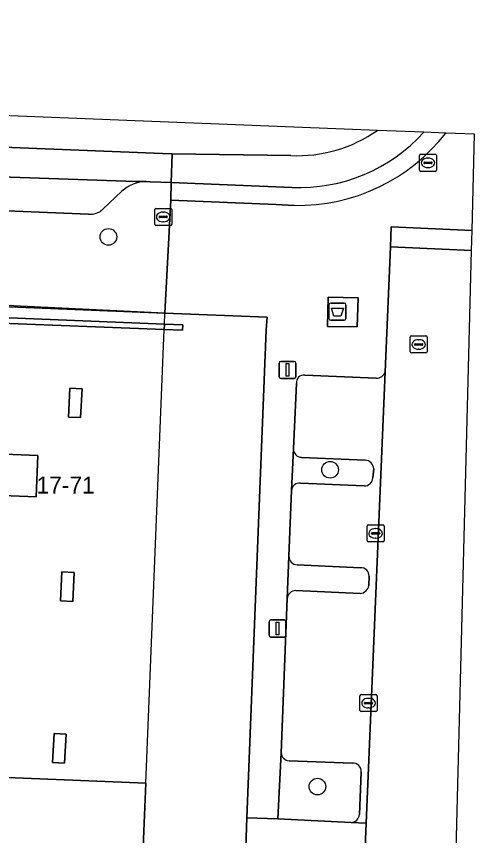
# Model space of a CAD drawing. Extents: x 160888 to 161385, y 386490 to 386908.
# Drawn here: x 161269.97 to 161296.87, y 386854.34 to 386902.41 of the extents above; entities that cross this region are included whole.
import ezdxf

# ---------------------------------------------------------------- set-up
doc = ezdxf.new("R2010")
doc.units = 0
for name, color, linetype in [('IMGEO_Afval_apart_plaats', 7, 'Continuous'), ('IMGEO_Boom', 7, 'Continuous'), ('IMGEO_Erf', 7, 'Continuous'), ('IMGEO_Groenvoorziening', 7, 'Continuous'), ('IMGEO_Hek', 7, 'Continuous'), ('IMGEO_Kolk', 7, 'Continuous'), ('IMGEO_Lichtmast', 7, 'Continuous'), ('IMGEO_Muur', 7, 'Continuous'), ('IMGEO_Pand', 7, 'Continuous'), ('IMGEO_Pand_nummerreeks', 7, 'Continuous'), ('IMGEO_Pand_overbouw', 7, 'Continuous'), ('IMGEO_Parkeervlak_gesloten', 7, 'Continuous'), ('IMGEO_Parkeervlak_open', 7, 'Continuous'), ('IMGEO_Rijbaan_lokaal_gesloten', 7, 'Continuous'), ('IMGEO_Rijbaan_lokaal_open', 7, 'Continuous'), ('IMGEO_Rioolput', 7, 'Continuous'), ('IMGEO_Voetpad_gesloten', 7, 'Continuous'), ('IMGEO_Voetpad_open', 7, 'Continuous')]:
    doc.layers.add(name, color=color, linetype=linetype)

msp = doc.modelspace()

# ---------------------------------------------------------------- linework, layer by layer
at = {"layer": 'IMGEO_Afval_apart_plaats'}
for p, q in [((161288.323, 386884.683), (161288.323, 386885.483)), ((161288.323, 386885.483), (161288.323, 386884.683)), ((161288.423, 386885.583), (161289.213, 386885.583)), ((161289.213, 386885.583), (161288.423, 386885.583)), ((161289.313, 386885.483), (161289.313, 386884.683)), ((161289.313, 386884.683), (161289.313, 386885.483)), ((161289.213, 386884.583), (161288.423, 386884.583)), ((161288.423, 386884.583), (161289.213, 386884.583))]:
    msp.add_line(p, q, dxfattribs=at)
msp.add_lwpolyline([(161288.466, 386885.297), (161289.17, 386885.297), (161289.021, 386884.827), (161288.615, 386884.827), (161288.466, 386885.297)], dxfattribs=at)
for centre, start, end in [((161288.423, 386885.483), 90, 180), ((161288.423, 386885.483), 90, 180), ((161289.213, 386885.483), 0, 90), ((161289.213, 386885.483), 360, 90), ((161288.423, 386884.683), 180, 270), ((161288.423, 386884.683), 180, 270), ((161289.213, 386884.683), 270, 0), ((161289.213, 386884.683), 270, 0)]:
    msp.add_arc(centre, 0.1, start, end, dxfattribs=at)
at = {"layer": 'IMGEO_Boom'}
for centre in [(161275.373, 386889.471), (161288.387, 386875.804), (161287.645, 386857.215)]:
    msp.add_circle(centre, 0.489, dxfattribs=at)
at = {"layer": 'IMGEO_Erf'}
for points in [[(161256.153, 386885.234), (161268.567, 386884.752), (161278.663, 386884.36), (161279.736, 386884.318), (161279.724, 386883.998), (161278.65, 386884.04), (161268.554, 386884.432), (161256.14, 386884.914)], [(161273.109, 386880.597), (161273.827, 386880.563), (161273.745, 386878.865), (161273.027, 386878.899)], [(161268.243, 386876.619), (161268.307, 386876.617), (161268.249, 386876.768), (161271.239, 386876.642), (161271.137, 386874.214), (161268.151, 386874.333), (161268.226, 386874.47), (161268.157, 386874.473)], [(161272.649, 386869.817), (161273.366, 386869.782), (161273.284, 386868.084), (161272.566, 386868.119)], [(161272.189, 386860.326), (161272.892, 386860.289), (161272.802, 386858.591), (161272.099, 386858.628)]]:
    msp.add_lwpolyline(points, close=True, dxfattribs=at)
msp.add_lwpolyline([(161267.493, 386857.839), (161277.574, 386857.417), (161277.385, 386852.718), (161283.395, 386852.488), (161283.497, 386855.383), (161284.645, 386884.014), (161284.686, 386884.758), (161278.689, 386885.003), (161268.594, 386885.414)], dxfattribs=at)
at = {"layer": 'IMGEO_Groenvoorziening'}
for points in [[(161286.232, 386877.048), (161286.131, 386874.595)], [(161290.445, 386876.371), (161286.716, 386876.537)], [(161290.902, 386875.327), (161290.948, 386875.86)], [(161286.642, 386875.03), (161290.395, 386874.859)], [(161285.97, 386870.742), (161285.872, 386868.246)], [(161290.183, 386870.06), (161286.454, 386870.23)], [(161290.661, 386869.015), (161290.68, 386869.559)], [(161286.385, 386868.722), (161290.145, 386868.551)], [(161285.519, 386859.207), (161285.322, 386855.328), (161289.625, 386855.121)], [(161289.691, 386858.597), (161285.989, 386858.735)], [(161290.109, 386855.573), (161290.208, 386858.067)]]:
    msp.add_lwpolyline(points, dxfattribs=at)
for centre, radius, start, end in [((161286.732, 386877.037), 0.5, 178.7551, 268.1361), ((161290.415, 386875.839), 0.533, 2.277, 86.8189), ((161290.409, 386875.353), 0.494, 268.4026, 357.0162), ((161286.602, 386874.559), 0.473, 85.1814, 175.6322), ((161286.479, 386870.739), 0.509, 179.6262, 267.1532), ((161290.193, 386869.573), 0.487, 358.3454, 91.1954), ((161290.115, 386869.103), 0.553, 273.0723, 350.853), ((161286.392, 386868.201), 0.522, 90.7175, 174.9974), ((161286.003, 386859.218), 0.484, 181.3596, 268.3971), ((161289.728, 386858.116), 0.483, 354.2201, 94.3572), ((161289.622, 386855.609), 0.488, 270.3229, 355.761)]:
    msp.add_arc(centre, radius, start, end, dxfattribs=at)
at = {"layer": 'IMGEO_Hek'}
msp.add_lwpolyline([(161284.645, 386884.014), (161283.497, 386855.383)], dxfattribs=at)
at = {"layer": 'IMGEO_Kolk'}
for p, q in [((161278.09, 386890.218), (161278.09, 386891.07)), ((161278.165, 386891.144), (161279.017, 386891.144)), ((161278.578, 386890.924), (161278.603, 386890.924)), ((161279.091, 386891.07), (161279.091, 386890.218)), ((161278.349, 386890.638), (161278.349, 386890.65)), ((161278.787, 386890.601), (161278.389, 386890.601)), ((161278.392, 386890.687), (161278.79, 386890.687)), ((161278.833, 386890.65), (161278.833, 386890.638)), ((161279.017, 386890.144), (161278.165, 386890.144)), ((161278.601, 386890.364), (161278.576, 386890.364)), ((161290.56, 386871.649), (161290.56, 386872.501)), ((161290.635, 386872.575), (161291.487, 386872.575)), ((161291.048, 386872.355), (161291.073, 386872.355)), ((161291.561, 386872.501), (161291.561, 386871.649)), ((161290.819, 386872.069), (161290.819, 386872.081)), ((161291.257, 386872.032), (161290.859, 386872.032)), ((161290.862, 386872.118), (161291.26, 386872.118)), ((161291.071, 386871.795), (161291.046, 386871.795)), ((161291.303, 386872.081), (161291.303, 386872.069)), ((161291.487, 386871.575), (161290.635, 386871.575)), ((161290.218, 386862.617), (161291.07, 386862.617)), ((161290.143, 386861.691), (161290.143, 386862.543)), ((161290.402, 386862.111), (161290.402, 386862.123)), ((161290.84, 386862.074), (161290.442, 386862.074)), ((161290.445, 386862.16), (161290.843, 386862.16)), ((161290.631, 386862.397), (161290.656, 386862.397)), ((161290.886, 386862.123), (161290.886, 386862.111)), ((161291.144, 386862.543), (161291.144, 386861.691)), ((161291.07, 386861.617), (161290.218, 386861.617)), ((161290.654, 386861.837), (161290.629, 386861.837))]:
    msp.add_line(p, q, dxfattribs=at)
for points in [[(161278.09, 386890.218), (161278.09, 386891.07)], [(161278.165, 386891.144), (161279.017, 386891.144)], [(161279.091, 386891.07), (161279.091, 386890.218)], [(161279.017, 386890.144), (161278.165, 386890.144)], [(161290.56, 386871.649), (161290.56, 386872.501)], [(161290.635, 386872.575), (161291.487, 386872.575)], [(161291.561, 386872.501), (161291.561, 386871.649)], [(161291.487, 386871.575), (161290.635, 386871.575)], [(161290.218, 386862.617), (161291.07, 386862.617)], [(161290.143, 386861.691), (161290.143, 386862.543)], [(161291.144, 386862.543), (161291.144, 386861.691)], [(161291.07, 386861.617), (161290.218, 386861.617)]]:
    msp.add_lwpolyline(points, dxfattribs=at)
for centre, radius, start, end in [((161278.167, 386891.068), 0.0765, 91.552, 178.448), ((161278.167, 386891.068), 0.0765, 91.552, 178.448), ((161279.015, 386891.068), 0.0765, 1.552, 88.448), ((161279.015, 386891.068), 0.0765, 1.552, 88.448), ((161278.389, 386890.647), 0.0403, 85.8775, 175.7526), ((161278.386, 386890.637), 0.0366, 178.938, 274.7102), ((161278.79, 386890.644), 0.043, 264.8664, 352.4533), ((161278.794, 386890.649), 0.0386, 1.7309, 96.639), ((161278.167, 386890.22), 0.0765, 181.552, 268.448), ((161278.167, 386890.22), 0.0765, 181.552, 268.448), ((161279.015, 386890.22), 0.0765, 271.552, 358.448), ((161279.015, 386890.22), 0.0765, 271.552, 358.448), ((161290.637, 386872.499), 0.0765, 91.552, 178.448), ((161290.637, 386872.499), 0.0765, 91.552, 178.448), ((161291.485, 386872.499), 0.0765, 1.552, 88.448), ((161291.485, 386872.499), 0.0765, 1.552, 88.448), ((161290.859, 386872.078), 0.0403, 85.8775, 175.7526), ((161290.856, 386872.068), 0.0366, 178.938, 274.7102), ((161291.26, 386872.075), 0.043, 264.8664, 352.4533), ((161291.264, 386872.08), 0.0386, 1.7309, 96.639), ((161290.637, 386871.651), 0.0765, 181.552, 268.448), ((161290.637, 386871.651), 0.0765, 181.552, 268.448), ((161291.485, 386871.651), 0.0765, 271.552, 358.448), ((161291.485, 386871.651), 0.0765, 271.552, 358.448), ((161290.22, 386862.541), 0.0765, 91.552, 178.448), ((161290.22, 386862.541), 0.0765, 91.552, 178.448), ((161291.068, 386862.541), 0.0765, 1.552, 88.448), ((161291.068, 386862.541), 0.0765, 1.552, 88.448), ((161290.442, 386862.12), 0.0403, 85.8775, 175.7526), ((161290.439, 386862.11), 0.0366, 178.938, 274.7102), ((161290.843, 386862.117), 0.043, 264.8664, 352.4533), ((161290.847, 386862.122), 0.0386, 1.7309, 96.639), ((161290.22, 386861.693), 0.0765, 181.552, 268.448), ((161290.22, 386861.693), 0.0765, 181.552, 268.448), ((161291.068, 386861.693), 0.0765, 271.552, 358.448), ((161291.068, 386861.693), 0.0765, 271.552, 358.448)]:
    msp.add_arc(centre, radius, start, end, dxfattribs=at)
for centre, major_axis, ratio, start_param, end_param in [((161278.577, 386890.644), (-0.387, 0.002), 0.722429, 4.712389, 7.853982), ((161278.602, 386890.644), (-0.39, 0.002), 0.717154, 1.570796, 4.712389), ((161291.047, 386872.075), (-0.387, 0.002), 0.722429, 4.712389, 7.853982), ((161291.072, 386872.075), (-0.39, 0.002), 0.717154, 1.570796, 4.712389), ((161290.63, 386862.117), (-0.387, 0.002), 0.722429, 4.712389, 7.853982), ((161290.655, 386862.117), (-0.39, 0.002), 0.717154, 1.570796, 4.712389)]:
    msp.add_ellipse(centre, major_axis=major_axis, ratio=ratio, start_param=start_param, end_param=end_param, dxfattribs=at)
at = {"layer": 'IMGEO_Lichtmast'}
for p, q in [((161285.393, 386881.265), (161285.393, 386882.065)), ((161285.393, 386882.065), (161285.393, 386881.265)), ((161285.493, 386882.165), (161286.283, 386882.165)), ((161286.283, 386882.165), (161285.493, 386882.165)), ((161286.383, 386882.065), (161286.383, 386881.265)), ((161286.383, 386881.265), (161286.383, 386882.065)), ((161286.283, 386881.165), (161285.493, 386881.165)), ((161285.493, 386881.165), (161286.283, 386881.165)), ((161284.806, 386866.095), (161284.806, 386866.895)), ((161284.806, 386866.895), (161284.806, 386866.095)), ((161284.906, 386866.995), (161285.696, 386866.995)), ((161285.696, 386866.995), (161284.906, 386866.995)), ((161285.796, 386866.895), (161285.796, 386866.095)), ((161285.796, 386866.095), (161285.796, 386866.895)), ((161285.696, 386865.995), (161284.906, 386865.995)), ((161284.906, 386865.995), (161285.696, 386865.995))]:
    msp.add_line(p, q, dxfattribs=at)
for points in [[(161285.813, 386882.04), (161285.963, 386882.04), (161285.963, 386881.29), (161285.813, 386881.29), (161285.813, 386882.04)], [(161285.226, 386866.87), (161285.376, 386866.87), (161285.376, 386866.12), (161285.226, 386866.12), (161285.226, 386866.87)]]:
    msp.add_lwpolyline(points, dxfattribs=at)
for centre, start, end in [((161285.493, 386882.065), 90, 180), ((161285.493, 386882.065), 90, 180), ((161286.283, 386882.065), 0, 90), ((161286.283, 386882.065), 360, 90), ((161285.493, 386881.265), 180, 270), ((161285.493, 386881.265), 180, 270), ((161286.283, 386881.265), 270, 0), ((161286.283, 386881.265), 270, 0), ((161284.906, 386866.895), 90, 180), ((161284.906, 386866.895), 90, 180), ((161285.696, 386866.895), 0, 90), ((161285.696, 386866.895), 360, 90), ((161284.906, 386866.095), 180, 270), ((161284.906, 386866.095), 180, 270), ((161285.696, 386866.095), 270, 0), ((161285.696, 386866.095), 270, 0)]:
    msp.add_arc(centre, 0.1, start, end, dxfattribs=at)
at = {"layer": 'IMGEO_Muur'}
for points in [[(161268.567, 386884.752), (161268.554, 386884.432), (161278.65, 386884.04), (161278.663, 386884.36)], [(161279.724, 386883.998), (161279.736, 386884.318), (161278.663, 386884.36), (161278.65, 386884.04)]]:
    msp.add_lwpolyline(points, close=True, dxfattribs=at)
at = {"layer": 'IMGEO_Pand'}
msp.add_lwpolyline([(161208.047, 386882.906), (161205.549, 386883.004), (161205.23, 386883.017), (161203.943, 386850.322), (161203.707, 386843.159), (161282.19, 386840.045), (161283.986, 386839.974), (161284.468, 386852.014), (161284.901, 386852.005), (161284.908, 386852.43), (161283.395, 386852.488), (161277.385, 386852.718), (161277.574, 386857.417), (161267.493, 386857.839), (161267.366, 386854.695), (161257.979, 386855.044), (161254.641, 386855.168), (161254.804, 386859.3), (161254.82, 386859.706), (161248.886, 386860.967), (161238.86, 386863.105)], dxfattribs=at)
for points in [[(161273.827, 386880.563), (161273.109, 386880.597), (161273.027, 386878.899), (161273.745, 386878.865)], [(161271.137, 386874.214), (161271.239, 386876.642), (161268.249, 386876.768), (161268.307, 386876.617), (161268.243, 386876.619), (161268.157, 386874.473), (161268.226, 386874.47), (161268.151, 386874.333)], [(161272.649, 386869.817), (161272.566, 386868.119), (161273.284, 386868.084), (161273.366, 386869.782)], [(161272.892, 386860.289), (161272.189, 386860.326), (161272.099, 386858.628), (161272.802, 386858.591)]]:
    msp.add_lwpolyline(points, close=True, dxfattribs=at)
at = {"layer": 'IMGEO_Pand_overbouw'}
msp.add_lwpolyline([(161268.597, 386885.494), (161268.594, 386885.414), (161268.567, 386884.752), (161268.554, 386884.432), (161268.249, 386876.768), (161271.239, 386876.642), (161271.137, 386874.214), (161268.151, 386874.333), (161267.493, 386857.839), (161277.574, 386857.417), (161278.65, 386884.04), (161278.663, 386884.36), (161278.689, 386885.003)], close=True, dxfattribs=at)
at = {"layer": 'IMGEO_Parkeervlak_gesloten'}
for points in [[(161277.593, 386892.717), (161276.971, 386892.717), (161258.887, 386893.342), (161258.81, 386891.423), (161274.2, 386890.804)], [(161275.046, 386891.089), (161276.17, 386892.15)]]:
    msp.add_lwpolyline(points, dxfattribs=at)
for centre, radius, start, end in [((161277.62, 386890.58), 2.137, 90.723, 132.727), ((161274.309, 386891.879), 1.08, 264.2072, 313.028)]:
    msp.add_arc(centre, radius, start, end, dxfattribs=at)
at = {"layer": 'IMGEO_Parkeervlak_open'}
for points in [[(161291.087, 386881.182), (161286.903, 386881.36)], [(161289.625, 386855.121), (161290.502, 386855.078), (161291.625, 386881.556)], [(161286.409, 386880.878), (161286.232, 386877.048)], [(161286.716, 386876.537), (161290.445, 386876.371)], [(161290.948, 386875.86), (161290.902, 386875.327)], [(161286.131, 386874.595), (161285.97, 386870.742)], [(161290.395, 386874.859), (161286.642, 386875.03)], [(161286.454, 386870.23), (161290.183, 386870.06)], [(161290.68, 386869.559), (161290.661, 386869.015)], [(161290.145, 386868.551), (161286.385, 386868.722)], [(161285.872, 386868.246), (161285.519, 386859.207)], [(161285.989, 386858.735), (161289.691, 386858.597)], [(161290.208, 386858.067), (161290.109, 386855.573)]]:
    msp.add_lwpolyline(points, dxfattribs=at)
for centre, radius, start, end in [((161286.86, 386880.91), 0.453, 84.5982, 183.9929), ((161291.109, 386881.725), 0.543, 267.73, 341.8815), ((161286.732, 386877.037), 0.5, 178.7551, 268.1361), ((161290.415, 386875.839), 0.533, 2.277, 86.8189), ((161290.409, 386875.353), 0.494, 268.4026, 357.0162), ((161286.602, 386874.559), 0.473, 85.1814, 175.6322), ((161286.479, 386870.739), 0.509, 179.6262, 267.1532), ((161290.193, 386869.573), 0.487, 358.3454, 91.1954), ((161290.115, 386869.103), 0.553, 273.0723, 350.853), ((161286.392, 386868.201), 0.522, 90.7175, 174.9974), ((161286.003, 386859.218), 0.484, 181.3596, 268.3971), ((161289.728, 386858.116), 0.483, 354.2201, 94.3572), ((161289.622, 386855.609), 0.488, 270.3229, 355.761)]:
    msp.add_arc(centre, radius, start, end, dxfattribs=at)
at = {"layer": 'IMGEO_Rijbaan_lokaal_gesloten'}
for points in [[(161291.165, 386895.721), (161123.374, 386902.409), (161123.263, 386900.56), (161248.069, 386895.57), (161278.544, 386894.358), (161279.11, 386894.349), (161286.088, 386894.243)], [(161293.896, 386895.612), (161291.165, 386895.721)], [(161286.088, 386894.243), (161279.11, 386894.349), (161279.059, 386892.659), (161286.148, 386892.369)]]:
    msp.add_lwpolyline(points, dxfattribs=at)
msp.add_lwpolyline([(161279.11, 386894.349), (161278.544, 386894.358), (161248.069, 386895.57), (161123.263, 386900.56), (161123.188, 386898.901), (161155.904, 386897.594), (161176.778, 386896.8), (161194.86, 386896.072), (161209.056, 386895.484), (161221.008, 386894.938), (161241.882, 386894.123), (161247.927, 386893.867), (161258.887, 386893.342), (161276.971, 386892.717), (161277.593, 386892.717), (161277.832, 386892.705), (161279.059, 386892.659)], close=True, dxfattribs=at)
for centre, radius, start, end in [((161286.454, 386902.445), 8.211, 267.4462, 305.0109), ((161286.454, 386902.445), 8.211, 267.4462, 305.0109), ((161286.549, 386902.289), 9.928, 267.6839, 317.7351)]:
    msp.add_arc(centre, radius, start, end, dxfattribs=at)
at = {"layer": 'IMGEO_Rijbaan_lokaal_open'}
for points in [[(161295.749, 386851.961), (161296.697, 386888.665), (161296.697, 386888.665), (161291.93, 386888.882), (161291.625, 386881.556), (161290.502, 386855.078), (161290.382, 386852.207), (161293.804, 386852.031)], [(161283.497, 386855.383), (161283.395, 386852.488), (161284.908, 386852.43), (161290.382, 386852.207), (161290.502, 386855.078), (161289.625, 386855.121), (161285.322, 386855.328)]]:
    msp.add_lwpolyline(points, close=True, dxfattribs=at)
at = {"layer": 'IMGEO_Rioolput'}
for p, q in [((161293.71, 386894.317), (161294.562, 386894.317)), ((161293.635, 386893.391), (161293.635, 386894.243)), ((161293.894, 386893.811), (161293.894, 386893.823)), ((161293.937, 386893.86), (161294.335, 386893.86)), ((161294.123, 386894.097), (161294.148, 386894.097)), ((161294.378, 386893.823), (161294.378, 386893.811)), ((161294.636, 386894.243), (161294.636, 386893.391)), ((161294.562, 386893.317), (161293.71, 386893.317)), ((161294.332, 386893.774), (161293.934, 386893.774)), ((161294.146, 386893.537), (161294.121, 386893.537)), ((161293.087, 386882.735), (161293.087, 386883.587)), ((161293.162, 386883.661), (161294.014, 386883.661)), ((161293.575, 386883.441), (161293.6, 386883.441)), ((161294.088, 386883.587), (161294.088, 386882.735)), ((161293.346, 386883.155), (161293.346, 386883.167)), ((161293.784, 386883.118), (161293.386, 386883.118)), ((161293.389, 386883.204), (161293.787, 386883.204)), ((161293.598, 386882.881), (161293.573, 386882.881)), ((161293.83, 386883.167), (161293.83, 386883.155)), ((161294.014, 386882.661), (161293.162, 386882.661))]:
    msp.add_line(p, q, dxfattribs=at)
for points in [[(161293.71, 386894.317), (161294.562, 386894.317)], [(161293.635, 386893.391), (161293.635, 386894.243)], [(161294.636, 386894.243), (161294.636, 386893.391)], [(161294.562, 386893.317), (161293.71, 386893.317)], [(161293.087, 386882.735), (161293.087, 386883.587)], [(161293.162, 386883.661), (161294.014, 386883.661)], [(161294.088, 386883.587), (161294.088, 386882.735)], [(161294.014, 386882.661), (161293.162, 386882.661)]]:
    msp.add_lwpolyline(points, dxfattribs=at)
for centre, radius, start, end in [((161293.712, 386894.241), 0.0765, 91.552, 178.448), ((161293.712, 386894.241), 0.0765, 91.552, 178.448), ((161294.56, 386894.241), 0.0765, 1.552, 88.448), ((161294.56, 386894.241), 0.0765, 1.552, 88.448), ((161293.934, 386893.82), 0.0403, 85.8775, 175.7526), ((161293.931, 386893.81), 0.0366, 178.938, 274.7102), ((161294.335, 386893.817), 0.043, 264.8664, 352.4533), ((161294.339, 386893.822), 0.0386, 1.7309, 96.639), ((161293.712, 386893.393), 0.0765, 181.552, 268.448), ((161293.712, 386893.393), 0.0765, 181.552, 268.448), ((161294.56, 386893.393), 0.0765, 271.552, 358.448), ((161294.56, 386893.393), 0.0765, 271.552, 358.448), ((161293.164, 386883.585), 0.0765, 91.552, 178.448), ((161293.164, 386883.585), 0.0765, 91.552, 178.448), ((161294.012, 386883.585), 0.0765, 1.552, 88.448), ((161294.012, 386883.585), 0.0765, 1.552, 88.448), ((161293.386, 386883.164), 0.0403, 85.8775, 175.7526), ((161293.383, 386883.154), 0.0366, 178.938, 274.7102), ((161293.787, 386883.161), 0.043, 264.8664, 352.4533), ((161293.791, 386883.166), 0.0386, 1.7309, 96.639), ((161293.164, 386882.737), 0.0765, 181.552, 268.448), ((161293.164, 386882.737), 0.0765, 181.552, 268.448), ((161294.012, 386882.737), 0.0765, 271.552, 358.448), ((161294.012, 386882.737), 0.0765, 271.552, 358.448)]:
    msp.add_arc(centre, radius, start, end, dxfattribs=at)
for centre, major_axis, ratio, start_param, end_param in [((161294.122, 386893.817), (-0.387, 0.002), 0.722429, 4.712389, 7.853982), ((161294.147, 386893.817), (-0.39, 0.002), 0.717154, 1.570796, 4.712389), ((161293.574, 386883.161), (-0.387, 0.002), 0.722429, 4.712389, 7.853982), ((161293.599, 386883.161), (-0.39, 0.002), 0.717154, 1.570796, 4.712389)]:
    msp.add_ellipse(centre, major_axis=major_axis, ratio=ratio, start_param=start_param, end_param=end_param, dxfattribs=at)
at = {"layer": 'IMGEO_Voetpad_gesloten'}
msp.add_lwpolyline([(161290.038, 386885.903), (161288.281, 386885.938), (161288.243, 386884.223), (161289.983, 386884.198)], close=True, dxfattribs=at)
at = {"layer": 'IMGEO_Voetpad_open'}
for points in [[(161274.2, 386890.804), (161258.81, 386891.423), (161256.885, 386891.501), (161256.805, 386890.402), (161250.217, 386890.662), (161250.255, 386891.79), (161247.831, 386891.89), (161241.794, 386892.138), (161239.425, 386892.236), (161239.41, 386891.107), (161235.397, 386891.29), (161235.468, 386892.398), (161220.937, 386892.996), (161208.945, 386893.49), (161207.063, 386893.567), (161206.996, 386892.136), (161196.74, 386892.515), (161196.781, 386894.009), (161194.801, 386894.087), (161176.703, 386894.8), (161176.66, 386894.802), (161176.601, 386893.617), (161155.57, 386894.474), (161155.616, 386895.637)], [(161291.625, 386881.556), (161291.93, 386888.882), (161291.979, 386890.06), (161296.728, 386889.843), (161296.874, 386895.493), (161295.179, 386895.561)], [(161295.179, 386895.561), (161293.896, 386895.612)], [(161127.058, 386890.969), (161178.427, 386888.94), (161188.186, 386888.554), (161196.395, 386888.23), (161196.381, 386887.886), (161205.414, 386887.602), (161205.385, 386886.913), (161206.029, 386886.888), (161210.581, 386886.706), (161222.369, 386886.248), (161222.396, 386887.248), (161239.793, 386886.567), (161249.896, 386886.171), (161268.594, 386885.414), (161278.689, 386885.003), (161279.034, 386891.63), (161279.059, 386892.659), (161277.832, 386892.705), (161277.593, 386892.717)], [(161286.148, 386892.369), (161279.059, 386892.659), (161279.034, 386891.63), (161285.229, 386891.364), (161286.28, 386891.319)], [(161276.17, 386892.15), (161275.046, 386891.089)], [(161286.28, 386891.319), (161285.229, 386891.364), (161279.034, 386891.63), (161278.689, 386885.003), (161284.686, 386884.758), (161284.645, 386884.014), (161283.497, 386855.383), (161285.322, 386855.328), (161285.519, 386859.207), (161285.872, 386868.246), (161285.97, 386870.742), (161286.131, 386874.595), (161286.232, 386877.048), (161286.409, 386880.878)], [(161286.903, 386881.36), (161291.087, 386881.182)]]:
    msp.add_lwpolyline(points, dxfattribs=at)
for points in [[(161296.728, 386889.843), (161291.979, 386890.06), (161291.93, 386888.882), (161296.697, 386888.665), (161296.697, 386888.665)], [(161288.243, 386884.223), (161288.281, 386885.938), (161290.038, 386885.903), (161289.983, 386884.198)]]:
    msp.add_lwpolyline(points, close=True, dxfattribs=at)
for centre, radius, start, end in [((161286.549, 386902.289), 9.928, 267.6839, 317.7351), ((161286.498, 386902.319), 11.002, 268.8671, 322.1008), ((161286.498, 386902.319), 11.002, 268.8671, 322.1008), ((161277.62, 386890.58), 2.137, 90.723, 132.727), ((161274.309, 386891.879), 1.08, 264.2072, 313.028), ((161286.86, 386880.91), 0.453, 84.5982, 183.9929), ((161291.109, 386881.725), 0.543, 267.73, 341.8815)]:
    msp.add_arc(centre, radius, start, end, dxfattribs=at)

# ---------------------------------------------------------------- texts
at = {"layer": 'IMGEO_Pand_nummerreeks'}
msp.add_text('17-71', height=1, dxfattribs=at).set_placement((161271.151, 386874.405))

doc.saveas('drawing.dxf')
